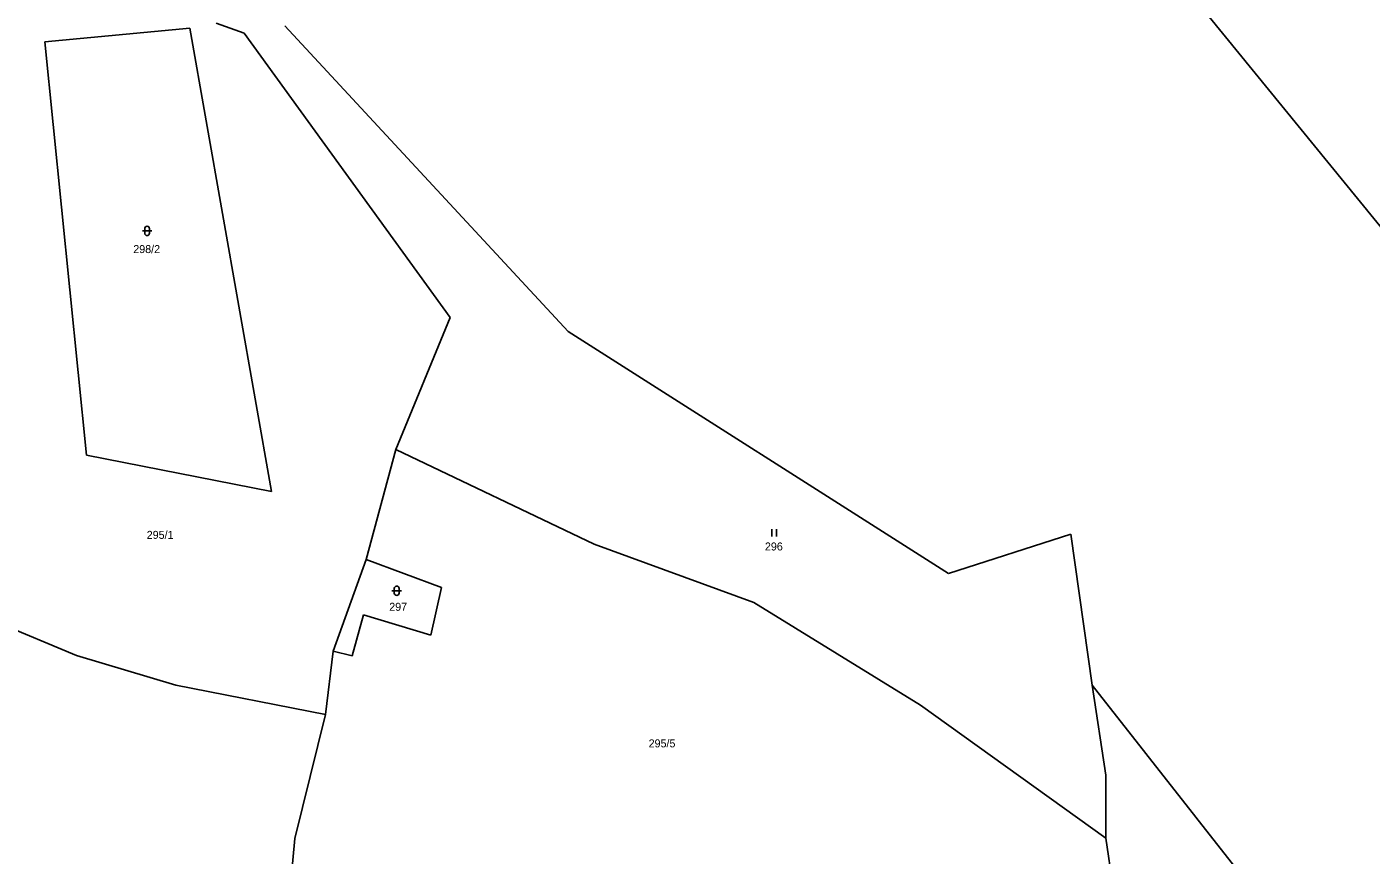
# Model space of a CAD drawing. Extents: x -765428 to -762163, y -1107632 to -1104975.
# Drawn here: x -763268.9 to -762983.3, y -1106897.8 to -1106721.8 of the extents above; entities that cross this region are included whole.
import ezdxf
from ezdxf.enums import TextEntityAlignment as Align

# ---------------------------------------------------------------- set-up
doc = ezdxf.new("R2010")
doc.units = 0
doc.header["$LTSCALE"] = 0.68
doc.layers.add('1', color=7, linetype='Continuous', lineweight=25)
doc.layers.add('3', color=7, linetype='Continuous', lineweight=25)
doc.layers.add('2', color=7, linetype='Continuous')

msp = doc.modelspace()

# ---------------------------------------------------------------- linework, layer by layer
at = {"layer": '1'}
for p, q in [((-763025.55, -1106710.08), (-762979.28, -1106766.78)), ((-763222.77, -1106723.14), (-763228.66, -1106721.05)), ((-763214.13, -1106721.59), (-763153.95, -1106786.57)), ((-763234.26, -1106722.07), (-763265.06, -1106724.98)), ((-763216.95, -1106820.55), (-763234.26, -1106722.07)), ((-763178.96, -1106783.59), (-763222.77, -1106723.14)), ((-763265.06, -1106724.98), (-763256.21, -1106812.8)), ((-763190.53, -1106811.63), (-763178.96, -1106783.59)), ((-763153.95, -1106786.57), (-763073.12, -1106837.99)), ((-763256.21, -1106812.8), (-763216.95, -1106820.55)), ((-763190.53, -1106811.63), (-763196.8, -1106834.99)), ((-763148.41, -1106831.78), (-763190.53, -1106811.63)), ((-763047.14, -1106829.62), (-763073.12, -1106837.99)), ((-763042.6, -1106861.72), (-763047.14, -1106829.62)), ((-763114.45, -1106844.14), (-763148.41, -1106831.78)), ((-763196.8, -1106834.99), (-763203.82, -1106854.46)), ((-763180.8, -1106840.93), (-763196.8, -1106834.99)), ((-763183.12, -1106851.1), (-763180.8, -1106840.93)), ((-763079.04, -1106865.96), (-763114.45, -1106844.14)), ((-763282.5, -1106845.36), (-763258.36, -1106855.43)), ((-763199.79, -1106855.49), (-763197.37, -1106846.76)), ((-763197.37, -1106846.76), (-763183.12, -1106851.1)), ((-763258.36, -1106855.43), (-763237.26, -1106861.69)), ((-763205.47, -1106867.95), (-763203.82, -1106854.46)), ((-763203.82, -1106854.46), (-763199.79, -1106855.49)), ((-763237.26, -1106861.69), (-763205.47, -1106867.95)), ((-762988.83, -1106930.16), (-763042.6, -1106861.72)), ((-763042.6, -1106861.72), (-763039.7, -1106880.85)), ((-763039.7, -1106894.24), (-763079.04, -1106865.96)), ((-763205.47, -1106867.95), (-763212, -1106894.32)), ((-763039.7, -1106880.85), (-763039.7, -1106894.24)), ((-763212, -1106894.32), (-763216.27, -1106940.94)), ((-763039.7, -1106894.24), (-763037.22, -1106910.8))]:
    msp.add_line(p, q, dxfattribs=at)
at = {"layer": '3'}
for p, q in [((-763243.861, -1106764.691), (-763243.861, -1106765.692)), ((-763242.859, -1106765.692), (-763242.859, -1106764.691)), ((-763244.361, -1106765.191), (-763242.359, -1106765.191)), ((-763110.681, -1106830.09), (-763110.681, -1106828.59)), ((-763109.68, -1106830.09), (-763109.68, -1106828.59)), ((-763191.351, -1106841.651), (-763189.349, -1106841.651)), ((-763190.851, -1106841.151), (-763190.851, -1106842.152)), ((-763189.849, -1106842.152), (-763189.849, -1106841.151))]:
    msp.add_line(p, q, dxfattribs=at)
for centre, start, end in [((-763243.36, -1106764.6909), 0, 180), ((-763243.36, -1106765.6909), 180, 359.98789), ((-763190.35, -1106841.1509), 0, 180), ((-763190.35, -1106842.1509), 180, 359.98789)]:
    msp.add_arc(centre, 0.5, start, end, dxfattribs=at)

# ---------------------------------------------------------------- texts
at = {"layer": '2'}
for s, p in [('298/2', (-763246.3, -1106769.895)), ('296', (-763112.12, -1106833.085)), ('297', (-763191.93, -1106845.905))]:
    msp.add_text(s, height=1.7, dxfattribs=at).set_placement(p)
for s, p in [('295/1', (-763240.6, -1106830.625)), ('295/5', (-763133.98, -1106874.925))]:
    msp.add_text(s, height=1.7, dxfattribs=at).set_placement(p, align=Align.CENTER)

doc.saveas('drawing.dxf')
